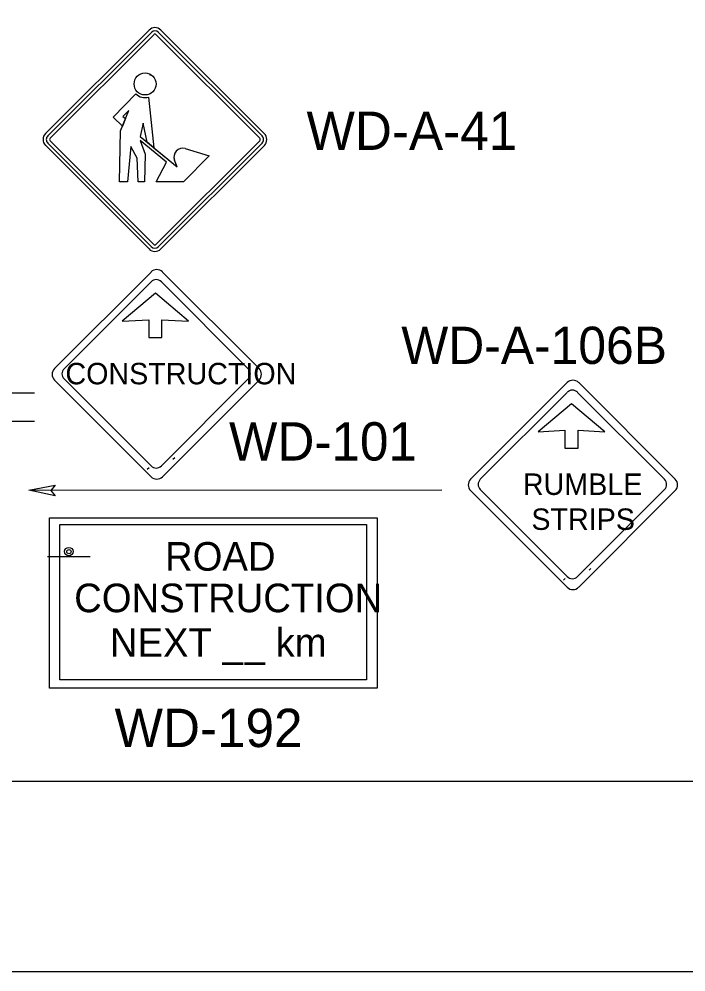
# Model space of a CAD drawing. Extents: x 1372 to 1588, y 125 to 404.
# Drawn here: x 1475.8 to 1513.7, y 125 to 179.1 of the extents above; entities that cross this region are included whole.
import ezdxf

# ---------------------------------------------------------------- set-up
doc = ezdxf.new("R2010")
doc.units = 0
for name, color, linetype in [('Level 1', 7, 'Continuous'), ('Level 10', 7, 'Continuous'), ('Level 2', 7, 'Continuous'), ('Level 44', 7, 'Continuous'), ('Level 5', 7, 'Continuous'), ('Level 60', 7, 'Continuous')]:
    doc.layers.add(name, color=color, linetype=linetype)

msp = doc.modelspace()

# ---------------------------------------------------------------- linework, layer by layer
at = {"layer": 'Level 1'}
for p, q in [((1483.204, 178.473), (1477.316, 172.592)), ((1483.335, 178.342), (1477.447, 172.461)), ((1483.466, 178.211), (1477.578, 172.331)), ((1489.492, 172.327), (1483.607, 178.211)), ((1489.622, 172.458), (1483.738, 178.341)), ((1489.753, 172.588), (1483.869, 178.472)), ((1483.261, 175.895), (1483.246, 175.895)), ((1477.578, 172.189), (1483.462, 166.305)), ((1483.603, 166.305), (1489.491, 172.185)), ((1477.315, 171.927), (1483.2, 166.042)), ((1477.447, 172.058), (1483.331, 166.174)), ((1483.735, 166.174), (1489.622, 172.054)), ((1483.865, 166.042), (1489.753, 171.923))]:
    msp.add_line(p, q, dxfattribs=at)
for points in [[(1481.719, 173.566), (1481.861, 173.446), (1481.691, 173.021), (1481.158, 173.526), (1482.442, 174.85)], [(1481.719, 173.566), (1481.861, 173.446), (1481.691, 173.021), (1481.158, 173.526), (1482.442, 174.85)], [(1482.159, 171.867), (1481.97, 169.86), (1481.52, 169.86), (1481.581, 172.743), (1481.692, 173.02), (1481.158, 173.526), (1482.442, 174.85)], [(1483.177, 174.662), (1483.475, 171.791), (1483.092, 172.107), (1482.875, 173.177), (1482.697, 172.432), (1484.793, 170.702), (1484.648, 171.077)], [(1483.177, 174.662), (1483.475, 171.791), (1483.092, 172.107), (1482.875, 173.177), (1482.697, 172.432), (1484.793, 170.702), (1484.648, 171.077)], [(1483.177, 174.662), (1483.475, 171.79), (1484.793, 170.702), (1484.648, 171.077)], [(1485.26, 171.739), (1486.611, 171.335), (1485.15, 169.86), (1483.612, 169.86), (1484.189, 170.972), (1482.696, 172.195), (1482.988, 171.416), (1482.95, 169.86), (1482.584, 169.86), (1482.518, 171.189), (1482.159, 171.867), (1481.97, 169.86), (1481.52, 169.86), (1481.581, 172.743), (1482.045, 173.901), (1481.719, 173.566)], [(1485.26, 171.739), (1486.611, 171.335), (1485.15, 169.86), (1483.612, 169.86), (1484.189, 170.972), (1482.696, 172.195), (1482.988, 171.416), (1482.95, 169.86), (1482.584, 169.86), (1482.518, 171.189), (1482.159, 171.867), (1481.97, 169.86), (1481.52, 169.86), (1481.581, 172.743), (1482.045, 173.901), (1481.719, 173.566)], [(1485.26, 171.739), (1486.611, 171.335), (1485.15, 169.86), (1483.612, 169.86), (1484.189, 170.972), (1482.696, 172.195), (1482.988, 171.416), (1482.95, 169.86), (1482.584, 169.86), (1482.518, 171.189), (1482.159, 171.867)]]:
    msp.add_lwpolyline(points, dxfattribs=at)
for points in [[(1481.719, 173.566), (1481.862, 173.446), (1482.045, 173.901)], [(1483.092, 172.105), (1482.875, 173.177), (1482.697, 172.432)]]:
    msp.add_lwpolyline(points, close=True, dxfattribs=at)
msp.add_circle((1482.977, 175.411), 0.624, dxfattribs=at)
msp.add_circle((1482.977, 175.411), 0.624, dxfattribs=at)
msp.add_circle((1482.977, 175.411), 0.624, dxfattribs=at)
for centre, radius, start, end in [((1483.536, 178.14), 0.471, 45, 134.9651), ((1483.536, 178.14), 0.285, 45, 134.9651), ((1483.536, 178.14), 0.1, 45, 134.9651), ((1482.977, 175.411), 0.775, 226.3135, 284.9576), ((1482.977, 175.411), 0.775, 226.3135, 284.9576), ((1482.977, 175.411), 0.775, 226.3135, 284.9576), ((1477.648, 172.259), 0.471, 134.965, 225), ((1477.648, 172.259), 0.285, 134.965, 225), ((1477.648, 172.259), 0.1, 134.965, 225), ((1489.42, 172.256), 0.1, 314.9651, 45), ((1489.42, 172.256), 0.285, 314.9651, 45), ((1489.42, 172.256), 0.471, 314.9651, 45), ((1485.116, 171.257), 0.502, 73.381, 201.0999), ((1485.116, 171.257), 0.502, 73.381, 201.0999), ((1485.116, 171.257), 0.502, 73.381, 201.0999), ((1483.532, 166.375), 0.285, 225, 314.9652), ((1483.532, 166.375), 0.1, 225, 314.9652), ((1483.532, 166.375), 0.471, 225, 314.9652)]:
    msp.add_arc(centre, radius, start, end, dxfattribs=at)
at = {"layer": 'Level 2'}
for p, q in [((1484.659, 154.179), (1484.555, 154.075)), ((1483.201, 153.612), (1483.097, 153.508)), ((1508.303, 147.898), (1508.199, 147.794)), ((1506.845, 147.331), (1506.741, 147.227))]:
    msp.add_line(p, q, dxfattribs=at)
for points in [[(1477.544, 150.763), (1496.168, 150.763), (1496.168, 141.104), (1477.544, 141.104)], [(1478.129, 150.383), (1495.554, 150.383), (1495.554, 141.573), (1478.129, 141.573)]]:
    msp.add_lwpolyline(points, close=True, dxfattribs=at)
at = {"layer": 'Level 44'}
for p, q in [((1483.317, 164.731), (1477.823, 159.246)), ((1489.451, 159.246), (1483.966, 164.731)), ((1478.374, 159.241), (1483.317, 164.178)), ((1483.901, 164.178), (1488.839, 159.241)), ((1483.559, 163.531), (1481.671, 161.94)), ((1485.446, 161.94), (1483.559, 163.531)), ((1481.671, 161.94), (1483.18, 162.021)), ((1483.18, 162.021), (1483.18, 161.013)), ((1483.937, 161.013), (1483.937, 162.021)), ((1483.937, 162.021), (1485.446, 161.94)), ((1483.18, 161.013), (1483.932, 161.013)), ((1477.823, 158.595), (1483.317, 153.104)), ((1477.828, 158.595), (1477.823, 158.595)), ((1483.317, 153.714), (1478.374, 158.655)), ((1488.839, 158.655), (1483.901, 153.714)), ((1483.966, 153.104), (1489.451, 158.595)), ((1506.961, 158.45), (1501.467, 152.965)), ((1513.095, 152.965), (1507.61, 158.45)), ((1457.984, 157.871), (1476.699, 157.871)), ((1502.018, 152.96), (1506.961, 157.897)), ((1507.545, 157.897), (1512.483, 152.96)), ((1507.203, 157.25), (1505.315, 155.659)), ((1509.09, 155.659), (1507.203, 157.25)), ((1458.284, 156.254), (1476.699, 156.254)), ((1505.315, 155.659), (1506.824, 155.74)), ((1506.824, 155.74), (1506.824, 154.732)), ((1507.581, 154.732), (1507.581, 155.74)), ((1507.581, 155.74), (1509.09, 155.659)), ((1506.824, 154.732), (1507.576, 154.732)), ((1501.467, 152.314), (1506.961, 146.823)), ((1501.472, 152.314), (1501.467, 152.314)), ((1506.961, 147.433), (1502.018, 152.374)), ((1512.483, 152.374), (1507.545, 147.433)), ((1507.61, 146.823), (1513.095, 152.314)), ((1477.434, 148.578), (1479.854, 148.578))]:
    msp.add_line(p, q, dxfattribs=at)
for radius in [0.242, 0.121]:
    msp.add_circle((1478.649, 148.849), radius, dxfattribs=at)
for centre, radius, start, end in [((1483.64, 164.408), 0.459, 45, 135), ((1483.608, 163.887), 0.413, 45, 135), ((1478.152, 158.92), 0.459, 135, 225), ((1478.668, 158.948), 0.413, 135, 225), ((1488.547, 158.948), 0.413, 315, 45), ((1489.129, 158.92), 0.459, 315, 45), ((1507.284, 158.127), 0.459, 45, 135), ((1507.251, 157.606), 0.413, 45, 135), ((1483.608, 154.008), 0.413, 225, 315), ((1483.64, 153.431), 0.459, 225, 315), ((1501.796, 152.639), 0.459, 135, 225), ((1502.312, 152.666), 0.413, 135, 225), ((1512.191, 152.666), 0.413, 315, 45), ((1512.772, 152.639), 0.459, 315, 45), ((1507.251, 147.727), 0.413, 225, 315), ((1507.284, 147.15), 0.459, 225, 315)]:
    msp.add_arc(centre, radius, start, end, dxfattribs=at)
at = {"layer": 'Level 5'}
msp.add_line((1476.368, 152.345), (1499.837, 152.358), dxfattribs=at)
msp.add_lwpolyline([(1476.368, 152.345), (1477.873, 152.63), (1477.62, 152.324), (1477.863, 152.01)], close=True, dxfattribs=at)
at = {"layer": 'Level 60'}
for points in [[(1372.057, 403.977), (1588.057, 403.977), (1588.057, 124.977), (1372.057, 124.977)], [(1391.183, 393.168), (1578.057, 393.168), (1578.057, 135.786), (1391.183, 135.786)]]:
    msp.add_lwpolyline(points, close=True, dxfattribs=at)

# ---------------------------------------------------------------- texts
at = {"layer": 'Level 10'}
for s, height, p in [('WD-A-41', 2.1774, (1492.148, 171.666)), ('WD-A-106B', 2.116, (1497.532, 159.51)), ('WD-101', 2.1774, (1487.744, 154.024)), ('WD-192', 2.177, (1481.245, 137.75))]:
    msp.add_text(s, height=height, rotation=360, dxfattribs=at).set_placement(p)
at = {"layer": 'Level 44'}
for s, height, p in [('CONSTRUCTION', 1.21784, (1478.452, 158.352)), ('RUMBLE', 1.2178, (1504.441, 152.071)), ('STRIPS', 1.2178, (1504.923, 150.084)), ('ROAD', 1.625, (1484.11, 147.767)), ('CONSTRUCTION', 1.625, (1478.948, 145.408))]:
    msp.add_text(s, height=height, rotation=360, dxfattribs=at).set_placement(p)
msp.add_text('NEXT __ km', height=1.625, dxfattribs=at).set_placement((1480.975, 142.875))

doc.saveas('drawing.dxf')
